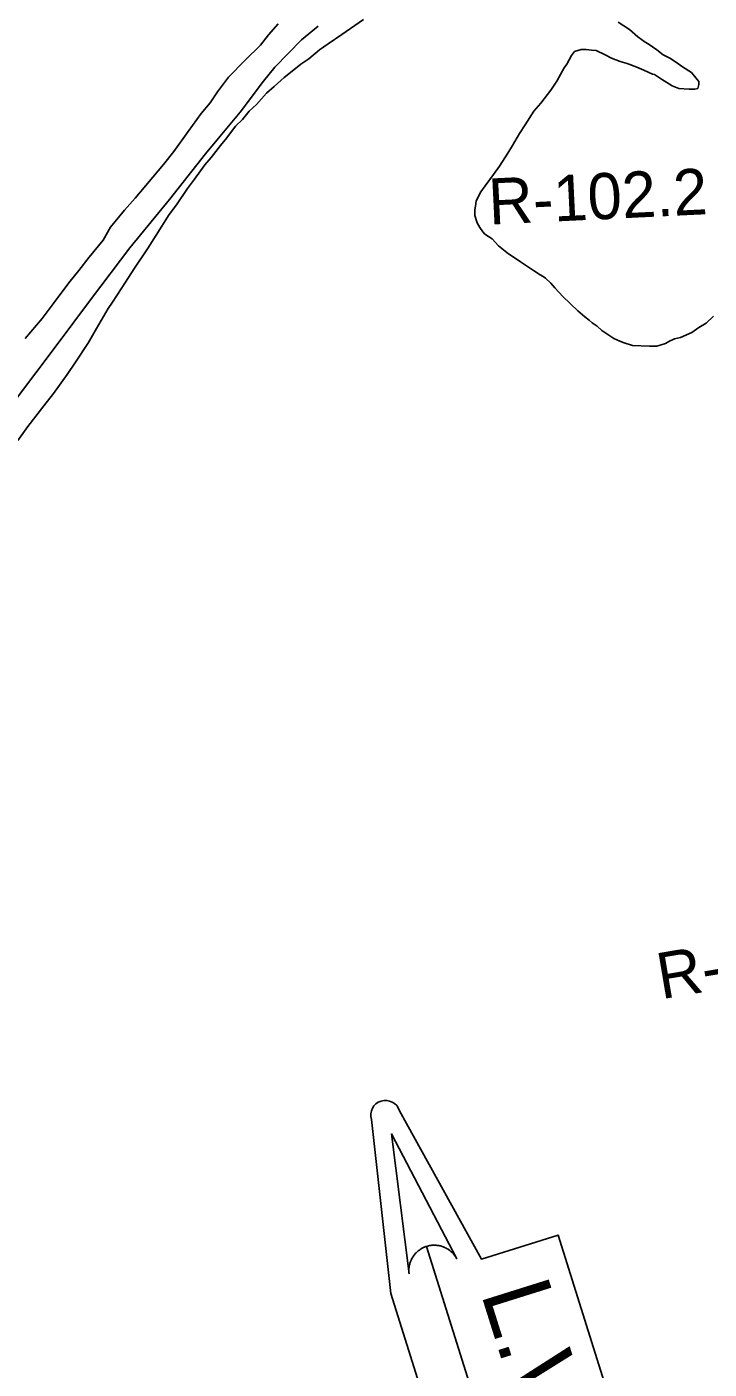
# Model space of a CAD drawing. Extents: x 3625074 to 3663148, y 511451 to 537151.
# Drawn here: x 3654402 to 3655631, y 518099 to 520518 of the extents above; entities that cross this region are included whole.
import ezdxf

# ---------------------------------------------------------------- set-up
doc = ezdxf.new("R2010")
doc.units = 0
for name, color, linetype in [('V-GRID-MAJR', 7, 'Continuous'), ('V-RIVR-RANG-IDEN', 7, 'Continuous'), ('V-SITE-VEGE', 7, 'Continuous'), ('V-TOPO-SHOR', 7, 'Continuous'), ('V-TOPO-WATR-IDEN', 7, 'Continuous')]:
    doc.layers.add(name, color=color, linetype=linetype)

msp = doc.modelspace()

# ---------------------------------------------------------------- linework, layer by layer
at = {"layer": 'V-GRID-MAJR'}
msp.add_spline([(3655702.3, 517125), (3655639.8, 523183.7), (3655577.2, 529244.4), (3655514.6, 535305), (3655514.6, 535306.9)], degree=3, dxfattribs=at)
at = {"layer": 'V-SITE-VEGE'}
for p, q in [((3654968.9, 520504.5), (3655008.2, 520531)), ((3655466.7, 520526.7), (3655487.2, 520513.1)), ((3654944.3, 520487.6), (3654968.9, 520504.5)), ((3655487.2, 520513.1), (3655502.3, 520500.1)), ((3655502.3, 520500.1), (3655515.8, 520490.2)), ((3654909.6, 520460.4), (3654928.9, 520476.4)), ((3654928.9, 520476.4), (3654944.3, 520487.6)), ((3655388.1, 520473.6), (3655382.7, 520466.5)), ((3655400.5, 520477), (3655388.1, 520473.6)), ((3655409.1, 520477.2), (3655400.5, 520477)), ((3655419.2, 520475.8), (3655409.1, 520477.2)), ((3655427.1, 520475.2), (3655419.2, 520475.8)), ((3655443.6, 520467.7), (3655427.1, 520475.2)), ((3655515.8, 520490.2), (3655521.3, 520487.2)), ((3655521.3, 520487.2), (3655536.4, 520476.5)), ((3655536.4, 520476.5), (3655548.2, 520467.4)), ((3654876.6, 520435.5), (3654895, 520450.7)), ((3654895, 520450.7), (3654909.6, 520460.4)), ((3655374.4, 520450.7), (3655369.9, 520444.4)), ((3655382.7, 520466.5), (3655374.4, 520450.7)), ((3655454.7, 520461.7), (3655443.6, 520467.7)), ((3655470.4, 520455.7), (3655454.7, 520461.7)), ((3655483, 520452.1), (3655470.4, 520455.7)), ((3655500.3, 520445.4), (3655483, 520452.1)), ((3655548.2, 520467.4), (3655560.1, 520461.4)), ((3655560.1, 520461.4), (3655571.9, 520453.8)), ((3655571.9, 520453.8), (3655583, 520446.2)), ((3654847.4, 520410.8), (3654865, 520426.7)), ((3654865, 520426.7), (3654876.6, 520435.5)), ((3655369.9, 520444.4), (3655356.3, 520419.9)), ((3655512.9, 520440.2), (3655500.3, 520445.4)), ((3655528.6, 520432.7), (3655512.9, 520440.2)), ((3655532.5, 520432), (3655528.6, 520432.7)), ((3655545.2, 520423.6), (3655532.5, 520432)), ((3655564.2, 520411.5), (3655545.2, 520423.6)), ((3655583, 520446.2), (3655598.8, 520435.6)), ((3655598.8, 520435.6), (3655606.8, 520426.4)), ((3655606.8, 520426.4), (3655612.4, 520419.5)), ((3654815.2, 520378.1), (3654833.5, 520398.8)), ((3654833.5, 520398.8), (3654847.4, 520410.8)), ((3655345.7, 520404.1), (3655327.4, 520380.3)), ((3655356.3, 520419.9), (3655345.7, 520404.1)), ((3655576, 520407), (3655564.2, 520411.5)), ((3655594.7, 520405.8), (3655576, 520407)), ((3655604.9, 520406), (3655594.7, 520405.8)), ((3655610.3, 520406.9), (3655604.9, 520406)), ((3655612.5, 520414), (3655610.3, 520406.9)), ((3655612.4, 520419.5), (3655612.5, 520414)), ((3654802.2, 520366.2), (3654815.2, 520378.1)), ((3655327.4, 520380.3), (3655315.2, 520366)), ((3654777.7, 520339.1), (3654790, 520351.1)), ((3654790, 520351.1), (3654802.2, 520366.2)), ((3655315.2, 520366), (3655299.3, 520341.5)), ((3654761.7, 520317.7), (3654777.7, 520339.1)), ((3655289.4, 520325.7), (3655276.6, 520304.4)), ((3655299.3, 520341.5), (3655289.4, 520325.7)), ((3654733.5, 520282.8), (3654750.3, 520304.2)), ((3654750.3, 520304.2), (3654761.7, 520317.7)), ((3655276.6, 520304.4), (3655268.3, 520290.1)), ((3654722.1, 520269.3), (3654733.5, 520282.8)), ((3655268.3, 520290.1), (3655253.1, 520267.2)), ((3654703.8, 520243.2), (3654722.1, 520269.3)), ((3655253.1, 520267.2), (3655242.5, 520252.2)), ((3654690.9, 520226.6), (3654703.8, 520243.2)), ((3655227.2, 520231.6), (3655219.6, 520220.5)), ((3655242.5, 520252.2), (3655227.2, 520231.6)), ((3654671.2, 520197.3), (3654690.9, 520226.6)), ((3655211.4, 520204.7), (3655210.7, 520199.2)), ((3655219.6, 520220.5), (3655211.4, 520204.7)), ((3654658.2, 520179.8), (3654671.2, 520197.3)), ((3655210.7, 520199.2), (3655208.6, 520187.5)), ((3655208.6, 520187.5), (3655208.8, 520178.1)), ((3654634.7, 520142.7), (3654658.2, 520179.8)), ((3655208.8, 520178.1), (3655212.9, 520164.9)), ((3655212.9, 520164.9), (3655217.8, 520156.4)), ((3655217.8, 520156.4), (3655223.4, 520148.7)), ((3654618.8, 520118.2), (3654634.7, 520142.7)), ((3655223.4, 520148.7), (3655226.6, 520144.1)), ((3655226.6, 520144.1), (3655240, 520135.8)), ((3655240, 520135.8), (3655251.2, 520123.5)), ((3654594.6, 520081), (3654618.8, 520118.2)), ((3655251.2, 520123.5), (3655269.5, 520109)), ((3655269.5, 520109), (3655279.7, 520102.2)), ((3655279.7, 520102.2), (3655290.8, 520094.6)), ((3655290.8, 520094.6), (3655314.6, 520078.7)), ((3654579.4, 520058.1), (3654594.6, 520081)), ((3655314.6, 520078.7), (3655326.4, 520071.1)), ((3655326.4, 520071.1), (3655331.9, 520068.1)), ((3655331.9, 520068.1), (3655335.9, 520065)), ((3655335.9, 520065), (3655345.5, 520055.8)), ((3654555.9, 520021.7), (3654579.4, 520058.1)), ((3655345.5, 520055.8), (3655352.7, 520047.4)), ((3655352.7, 520047.4), (3655367, 520032.1)), ((3654548.3, 520010.6), (3654555.9, 520021.7)), ((3655367, 520032.1), (3655394.1, 520006)), ((3654527.2, 519974.3), (3654548.3, 520010.6)), ((3655394.1, 520006), (3655406.8, 519995.4)), ((3655406.8, 519995.4), (3655414.7, 519989.3)), ((3655414.7, 519989.3), (3655420.2, 519984.7)), ((3655625.6, 519984), (3655638.7, 519996.8)), ((3654512.8, 519949), (3654527.2, 519974.3)), ((3655420.2, 519984.7), (3655429, 519978.6)), ((3655429, 519978.6), (3655437.7, 519971)), ((3655437.7, 519971), (3655459.1, 519956.5)), ((3655579.3, 519958.1), (3655599.4, 519967.1)), ((3655599.4, 519967.1), (3655612.5, 519975.9)), ((3655612.5, 519975.9), (3655625.6, 519984)), ((3654489.3, 519913.4), (3654512.8, 519949)), ((3655459.1, 519956.5), (3655470.1, 519951.3)), ((3655470.1, 519951.3), (3655478, 519948.3)), ((3655478, 519948.3), (3655492.9, 519943.9)), ((3655492.9, 519943.9), (3655523.4, 519942.2)), ((3655523.4, 519942.2), (3655536.6, 519942.4)), ((3655536.6, 519942.4), (3655552.2, 519947.4)), ((3655552.2, 519947.4), (3655558.3, 519950.7)), ((3655558.3, 519950.7), (3655568.4, 519955.6)), ((3655568.4, 519955.6), (3655579.3, 519958.1)), ((3654449.8, 519857.2), (3654474.1, 519891.2)), ((3654474.1, 519891.2), (3654489.3, 519913.4)), ((3654432.3, 519835), (3654449.8, 519857.2)), ((3654403.3, 519797.7), (3654432.3, 519835)), ((3654385.1, 519772.4), (3654403.3, 519797.7))]:
    msp.add_line(p, q, dxfattribs=at)
msp.add_lwpolyline([(3654854.5, 520523.3), (3654837, 520503.5), (3654822.5, 520485.2), (3654794.9, 520458.2), (3654765.1, 520427.1), (3654745.3, 520401), (3654731.6, 520381.2), (3654715.6, 520362.1), (3654692, 520329.6), (3654666.2, 520293.2), (3654647.9, 520270.2), (3654596.8, 520209.1), (3654577.6, 520187.6), (3654552.5, 520156.7), (3654538.9, 520133.8), (3654513.7, 520102.8), (3654495.4, 520079.1), (3654477.1, 520056.8), (3654449, 520018.8), (3654429.2, 519992.6), (3654398.7, 519956.1)], dxfattribs=at)
at = {"layer": 'V-TOPO-SHOR'}
msp.add_lwpolyline([(3654926.7, 520519.1), (3654896.5, 520494.6), (3654848.1, 520445.4), (3654827.9, 520419.9), (3654786, 520364.1), (3654749.8, 520320.8), (3654723.7, 520289.2), (3654658.8, 520207.1), (3654587.3, 520119.7), (3654518.2, 520028.7), (3654454.5, 519943), (3654381.1, 519846)], dxfattribs=at)
at = {"layer": 'V-TOPO-WATR-IDEN'}
msp.add_line((3655121.9, 518319.9), (3655346.8, 517603.2), dxfattribs=at)
for points in [[(3655073, 518564.5), (3655220.5, 518297), (3655358.6, 518340.3), (3655549.8, 517731.1), (3655411.7, 517687.8), (3655446.4, 517374.5)], [(3655395.8, 517358.7), (3655242.1, 517645.7), (3655181.2, 517839.8), (3655033, 517793.3), (3654976.4, 517973.6), (3655124.6, 518020.2), (3655057.3, 518234.7), (3655022.4, 518548.6)]]:
    msp.add_lwpolyline(points, dxfattribs=at)
msp.add_lwpolyline([(3655090.2, 518270.7), (3655058.3, 518522.6), (3655176.1, 518297.6), (3655173.8, 518301.6), (3655171.1, 518305.1), (3655170, 518306.5), (3655169, 518307.6), (3655167.6, 518309), (3655166.3, 518310.2), (3655165.1, 518311.3), (3655163.4, 518312.6), (3655161.5, 518314), (3655160.4, 518314.7), (3655159, 518315.6), (3655157.1, 518316.7), (3655155.5, 518317.5), (3655153.9, 518318.2), (3655152.7, 518318.7), (3655151.5, 518319.2), (3655149.9, 518319.7), (3655148.5, 518320.2), (3655147, 518320.6), (3655145.9, 518320.9), (3655144.1, 518321.3), (3655142.3, 518321.5), (3655140.9, 518321.7), (3655139.3, 518321.9), (3655137.9, 518322), (3655136.6, 518322), (3655135.6, 518322), (3655134.1, 518322), (3655132.6, 518321.9), (3655131.1, 518321.8), (3655129.6, 518321.6), (3655128.2, 518321.4), (3655126.8, 518321.2), (3655125.5, 518320.9), (3655123.8, 518320.5), (3655121.9, 518319.9), (3655121.3, 518319.7), (3655120.4, 518319.4), (3655119.4, 518319.1), (3655118.4, 518318.7), (3655117.5, 518318.3), (3655116.5, 518317.9), (3655115.5, 518317.4), (3655114.7, 518317), (3655113.6, 518316.4), (3655112.7, 518315.9), (3655112, 518315.5), (3655110.3, 518314.4), (3655109.4, 518313.8), (3655108.8, 518313.3), (3655107.8, 518312.6), (3655106.9, 518311.9), (3655106.1, 518311.2), (3655105, 518310.3), (3655104.1, 518309.5), (3655103.4, 518308.8), (3655102.8, 518308.2), (3655102, 518307.4), (3655101.3, 518306.6), (3655100.6, 518305.7), (3655099.8, 518304.8), (3655099.1, 518303.8), (3655098.1, 518302.5), (3655097.5, 518301.6), (3655096.9, 518300.6), (3655096.2, 518299.6), (3655095.7, 518298.7), (3655095.2, 518297.8), (3655094.5, 518296.4), (3655094.5, 518296.3), (3655094.1, 518295.5), (3655093.8, 518294.9), (3655093.4, 518293.9), (3655092.9, 518292.7), (3655092.6, 518291.8), (3655092.3, 518290.9), (3655091.9, 518289.8), (3655091.6, 518288.7), (3655091.4, 518287.9), (3655091.1, 518286.9), (3655090.8, 518285.4), (3655090.6, 518284.6), (3655090.5, 518283.9), (3655090.4, 518283.3), (3655090.3, 518282.6), (3655090.2, 518281.6), (3655090.1, 518280.6), (3655090, 518279.6), (3655089.9, 518278.7), (3655089.9, 518277.4), (3655089.9, 518276.7), (3655089.9, 518275.5), (3655089.9, 518274.1), (3655090, 518273.1), (3655090, 518272.3), (3655090.1, 518271.6), (3655090.2, 518271.1)], close=True, dxfattribs=at)
msp.add_arc((3655047.7, 518556.5), 26.5, 17.4226, 197.4226, dxfattribs=at)

# ---------------------------------------------------------------- texts
at = {"layer": 'V-RIVR-RANG-IDEN'}
for s, rotation, p in [('R-102.2', 2.7514, (3655235.1, 520161.5)), ('R-102.0', 9.6357, (3655544.6, 518765.2))]:
    msp.add_text(s, height=83, rotation=rotation, dxfattribs=at).set_placement(p)
at = {"layer": 'V-TOPO-WATR-IDEN'}
msp.add_text('L.W.R.P.', height=124.5, rotation=287.4226, dxfattribs=at).set_placement((3655219, 518236))

doc.saveas('drawing.dxf')
